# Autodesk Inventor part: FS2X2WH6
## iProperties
Shininess: 64.0
Length Units: 11272
Angle Units: 11279
Time Units: 11290
Mass Units: 11286
Length Display Precision: 3
Angle Display Precision: 2
Compacted: True
Part Number: FS2X2WH6
Document SubType Name: Modeling
Created: 2003-12
Designer: Charles Bliss
Manufacturer: Standard
Standards Organization: Custom
Catalog Web Link: http://www.panduit.com
Density: 0.0
Volumn: 0.0
Area: 0.0
PropertySet Name: Model Information
Control State: 0
Master: False
Checked Out: False
Author: Charles Bliss
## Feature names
1. Extrusion1
2. MountHoles [Extrusion]
3. MountHolePat [Rectangular Pattern]
